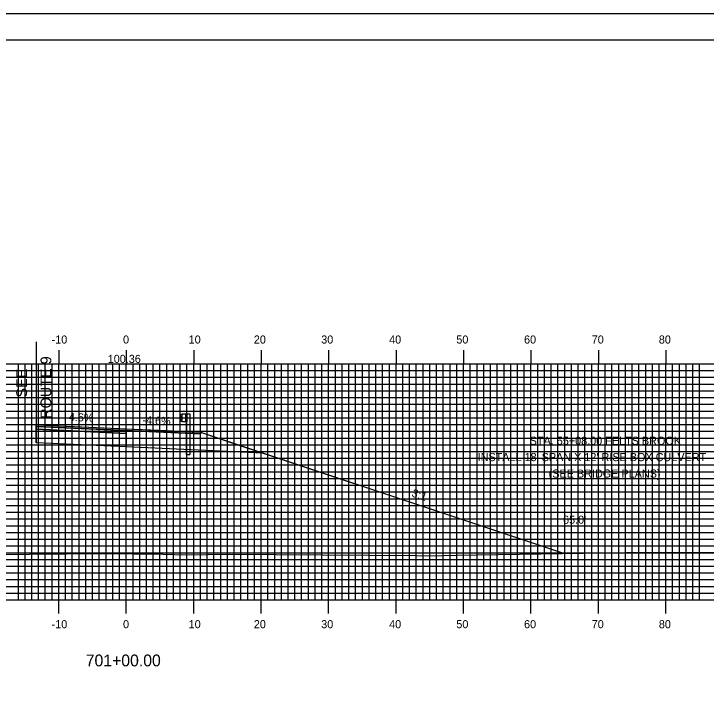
# Model space of a CAD drawing. Extents: x 852542 to 852886, y 364366 to 364586.
# Drawn here: x 852691.5 to 852794.1, y 364484.7 to 364585.7 of the extents above; entities that cross this region are included whole.
import ezdxf

# ---------------------------------------------------------------- set-up
doc = ezdxf.new("R2010")
doc.units = 0
for name, color, linetype in [('ANNOTATION', 7, 'Continuous'), ('BORDER', 7, 'Continuous'), ('D_Guardrail_Beam_Rt', 7, 'Continuous'), ('D_Roadway_Centerline', 7, 'Continuous'), ('D_Roadway_Centerline_Text', 7, 'Continuous'), ('D_Roadway_Edge_Shoulder', 7, 'Continuous'), ('D_Roadway_Edge_TW', 7, 'Continuous'), ('D_Roadway_Pavement', 7, 'Continuous'), ('D_Roadway_SlopeLines', 7, 'Continuous'), ('D_Roadway_SubGrade', 7, 'Continuous'), ('D_Text_Standard', 7, 'Continuous'), ('H_V ANNOTATION', 7, 'Continuous'), ('MAJOR', 7, 'Continuous'), ('MINOR', 7, 'Continuous'), ('PLOT BOUNDARY', 7, 'Continuous'), ('S_Roadway_Centerline', 7, 'Continuous')]:
    doc.layers.add(name, color=color, linetype=linetype)

msp = doc.modelspace()

# ---------------------------------------------------------------- linework, layer by layer
at = {"layer": 'BORDER'}
msp.add_lwpolyline([(852558.58, 364371.79), (852878.58, 364371.79), (852878.58, 364581.79), (852558.58, 364581.79)], close=True, dxfattribs=at)
at = {"layer": 'D_Guardrail_Beam_Rt'}
for p, q in [((852716.36, 364526.26), (852716.22, 364526.16)), ((852716.22, 364526.02), (852716.41, 364525.88)), ((852716.45, 364526.28), (852716.38, 364526.26)), ((852716.45, 364526.36), (852717.14, 364526.36)), ((852716.45, 364525.2), (852716.45, 364526.36)), ((852716.97, 364526.36), (852716.97, 364525.2)), ((852717.07, 364526.36), (852717.07, 364525.2)), ((852717.14, 364526.36), (852717.61, 364526.36)), ((852717.14, 364526.36), (852717.14, 364525.2)), ((852717.61, 364526.36), (852717.61, 364520.36)), ((852716.41, 364525.68), (852716.22, 364525.54)), ((852716.22, 364525.4), (852716.36, 364525.3)), ((852716.38, 364525.29), (852716.45, 364525.28)), ((852716.44, 364525.81), (852716.44, 364525.74)), ((852717.14, 364525.2), (852716.45, 364525.2)), ((852717.12, 364520.36), (852717.12, 364525.2)), ((852717.12, 364520.36), (852717.61, 364520.36))]:
    msp.add_line(p, q, dxfattribs=at)
for centre, major_axis, start_param, end_param in [((852716.27, 364526.09), (-0.0877, 0), 5.323254, 7.243116), ((852716.38, 364526.22), (-0.0417, 0), 4.907132, 5.323254), ((852716.27, 364525.47), (-0.0877, 0), 5.323254, 7.243116), ((852716.38, 364525.33), (-0.0417, 0), 0.959931, 1.376053), ((852716.37, 364525.81), (0.0789, 0), 0, 0.959931), ((852716.37, 364525.74), (0.0789, 0), 5.323254, 6.283185)]:
    msp.add_ellipse(centre, major_axis=major_axis, ratio=0.995501, start_param=start_param, end_param=end_param, dxfattribs=at)
at = {"layer": 'D_Roadway_Centerline'}
msp.add_lwpolyline([(852694.81, 364524.76), (852698.22, 364524.6), (852708.18, 364524.15), (852712.95, 364523.93), (852716.18, 364523.78), (852717.96, 364523.7), (852719.18, 364523.64), (852724.71, 364521.8), (852728.46, 364520.55), (852755.36, 364511.58), (852773.13, 364505.66)], dxfattribs=at)
at = {"layer": 'D_Roadway_Edge_Shoulder'}
for points in [[(852708.18, 364524.15), (852719.18, 364523.64), (852719.18, 364523.39), (852708.18, 364523.9)], [(852708.18, 364524.15), (852716.18, 364523.78), (852716.18, 364523.78), (852719.18, 364523.64), (852719.18, 364523.39), (852708.18, 364523.9)], [(852708.18, 364524.15), (852716.18, 364523.78), (852716.18, 364523.78), (852719.18, 364523.64), (852719.18, 364523.39), (852708.18, 364523.9)], [(852708.18, 364524.15), (852719.18, 364523.64), (852719.18, 364523.39), (852708.18, 364523.9)], [(852708.18, 364524.15), (852719.18, 364523.64), (852719.18, 364523.39), (852708.18, 364523.9)]]:
    msp.add_lwpolyline(points, close=True, dxfattribs=at)
at = {"layer": 'D_Roadway_Edge_TW'}
msp.add_lwpolyline([(852694.81, 364524.76), (852708.18, 364524.15), (852708.18, 364523.9), (852694.81, 364524.51)], close=True, dxfattribs=at)
msp.add_lwpolyline([(852694.81, 364524.76), (852708.18, 364524.15), (852708.18, 364523.9), (852694.81, 364524.51)], close=True, dxfattribs=at)
msp.add_lwpolyline([(852694.81, 364524.76), (852708.18, 364524.15), (852708.18, 364523.9), (852694.81, 364524.51)], close=True, dxfattribs=at)
msp.add_lwpolyline([(852694.81, 364524.76), (852708.18, 364524.15), (852708.18, 364523.9), (852694.81, 364524.51)], dxfattribs=at)
at = {"layer": 'D_Roadway_Pavement'}
msp.add_lwpolyline([(852694.81, 364524.51), (852708.18, 364523.9), (852708.18, 364523.48), (852694.81, 364524.09)], close=True, dxfattribs=at)
msp.add_lwpolyline([(852694.81, 364524.51), (852708.18, 364523.9), (852708.18, 364523.48), (852694.81, 364524.09)], close=True, dxfattribs=at)
msp.add_lwpolyline([(852694.81, 364524.51), (852708.18, 364523.9), (852708.18, 364523.48), (852694.81, 364524.09)], close=True, dxfattribs=at)
msp.add_lwpolyline([(852694.81, 364524.51), (852708.18, 364523.9), (852708.18, 364523.48), (852694.81, 364524.09)], close=True, dxfattribs=at)
msp.add_lwpolyline([(852708.18, 364523.9), (852708.18, 364523.48)], dxfattribs=at)
msp.add_lwpolyline([(852708.18, 364523.9), (852708.18, 364523.48)], dxfattribs=at)
msp.add_lwpolyline([(852708.18, 364523.9), (852708.18, 364523.48)], dxfattribs=at)
msp.add_lwpolyline([(852708.18, 364523.9), (852708.18, 364523.48)], dxfattribs=at)
msp.add_lwpolyline([(852708.18, 364523.9), (852708.18, 364523.48)], dxfattribs=at)
msp.add_lwpolyline([(852708.18, 364523.9), (852708.18, 364523.48)], dxfattribs=at)
msp.add_lwpolyline([(852708.18, 364523.9), (852708.18, 364523.48)], dxfattribs=at)
msp.add_lwpolyline([(852708.18, 364523.9), (852708.18, 364523.48)], dxfattribs=at)
msp.add_lwpolyline([(852708.18, 364523.9), (852708.18, 364523.48)], dxfattribs=at)
msp.add_lwpolyline([(852708.18, 364523.9), (852708.18, 364523.48)], dxfattribs=at)
msp.add_lwpolyline([(852708.18, 364523.9), (852708.18, 364523.48)], dxfattribs=at)
msp.add_lwpolyline([(852708.18, 364523.9), (852708.18, 364523.48)], dxfattribs=at)
msp.add_lwpolyline([(852708.18, 364523.9), (852708.18, 364523.48)], dxfattribs=at)
msp.add_lwpolyline([(852708.18, 364523.9), (852708.18, 364523.48)], dxfattribs=at)
at = {"layer": 'D_Roadway_SlopeLines'}
msp.add_lwpolyline([(852719.18, 364523.64), (852773.13, 364505.66)], dxfattribs=at)
msp.add_lwpolyline([(852719.18, 364523.64), (852773.13, 364505.66)], dxfattribs=at)
msp.add_lwpolyline([(852719.18, 364523.64), (852773.13, 364505.66)], dxfattribs=at)
msp.add_lwpolyline([(852719.18, 364523.64), (852773.13, 364505.66)], dxfattribs=at)
at = {"layer": 'D_Roadway_SubGrade'}
msp.add_line((852694.81, 364537.05), (852694.81, 364522.09), dxfattribs=at)
for points in [[(852694.81, 364524.09), (852708.18, 364523.48), (852708.18, 364521.48), (852694.81, 364522.09)], [(852694.81, 364524.09), (852708.18, 364523.48), (852708.18, 364521.48), (852694.81, 364522.09)], [(852694.81, 364524.09), (852708.18, 364523.48), (852708.18, 364521.48), (852694.81, 364522.09)], [(852694.81, 364524.09), (852708.18, 364523.48), (852708.18, 364521.48), (852694.81, 364522.09)], [(852708.18, 364523.48), (852708.18, 364523.9), (852719.18, 364523.39), (852719.18, 364523.64), (852728.46, 364520.55), (852708.18, 364521.48)], [(852708.18, 364523.48), (852708.18, 364523.9), (852719.18, 364523.39), (852719.18, 364523.64), (852728.46, 364520.55), (852708.18, 364521.48)], [(852708.18, 364523.48), (852708.18, 364523.9), (852719.18, 364523.39), (852719.18, 364523.64), (852728.46, 364520.55), (852708.18, 364521.48)], [(852708.18, 364523.48), (852708.18, 364523.9), (852719.18, 364523.39), (852719.18, 364523.64), (852728.46, 364520.55), (852708.18, 364521.48)]]:
    msp.add_lwpolyline(points, close=True, dxfattribs=at)
at = {"layer": 'MAJOR'}
for p, q in [((852698.18, 364535.79), (852698.18, 364533.79)), ((852708.18, 364535.79), (852708.18, 364533.79)), ((852718.18, 364535.79), (852718.18, 364533.79)), ((852728.18, 364535.79), (852728.18, 364533.79)), ((852738.18, 364535.79), (852738.18, 364533.79)), ((852748.18, 364535.79), (852748.18, 364533.79)), ((852758.18, 364535.79), (852758.18, 364533.79)), ((852768.18, 364535.79), (852768.18, 364533.79)), ((852778.18, 364535.79), (852778.18, 364533.79)), ((852788.18, 364535.79), (852788.18, 364533.79)), ((852568.18, 364533.79), (852848.18, 364533.79)), ((852568.18, 364533.79), (852848.18, 364533.79)), ((852698.18, 364498.79), (852698.18, 364533.79)), ((852708.18, 364498.79), (852708.18, 364533.79)), ((852718.18, 364498.79), (852718.18, 364533.79)), ((852728.18, 364498.79), (852728.18, 364533.79)), ((852738.18, 364498.79), (852738.18, 364533.79)), ((852748.18, 364498.79), (852748.18, 364533.79)), ((852758.18, 364498.79), (852758.18, 364533.79)), ((852768.18, 364498.79), (852768.18, 364533.79)), ((852778.18, 364498.79), (852778.18, 364533.79)), ((852788.18, 364498.79), (852788.18, 364533.79)), ((852568.18, 364528.79), (852848.18, 364528.79)), ((852568.18, 364523.79), (852848.18, 364523.79)), ((852568.18, 364518.79), (852848.18, 364518.79)), ((852568.18, 364513.79), (852848.18, 364513.79)), ((852568.18, 364508.79), (852848.18, 364508.79)), ((852568.18, 364503.79), (852848.18, 364503.79)), ((852568.18, 364498.79), (852848.18, 364498.79)), ((852568.18, 364498.79), (852848.18, 364498.79)), ((852698.18, 364496.78), (852698.18, 364498.79)), ((852708.18, 364496.78), (852708.18, 364498.79)), ((852718.18, 364496.78), (852718.18, 364498.79)), ((852728.18, 364496.78), (852728.18, 364498.79)), ((852738.18, 364496.78), (852738.18, 364498.79)), ((852748.18, 364496.78), (852748.18, 364498.79)), ((852758.18, 364496.78), (852758.18, 364498.79)), ((852768.18, 364496.78), (852768.18, 364498.79)), ((852778.18, 364496.78), (852778.18, 364498.79)), ((852788.18, 364496.78), (852788.18, 364498.79))]:
    msp.add_line(p, q, dxfattribs=at)
at = {"layer": 'MINOR'}
for p, q in [((852692.18, 364498.79), (852692.18, 364533.79)), ((852693.18, 364498.79), (852693.18, 364533.79)), ((852694.18, 364498.79), (852694.18, 364533.79)), ((852695.18, 364498.79), (852695.18, 364533.79)), ((852696.18, 364498.79), (852696.18, 364533.79)), ((852697.18, 364498.79), (852697.18, 364533.79)), ((852699.18, 364498.79), (852699.18, 364533.79)), ((852700.18, 364498.79), (852700.18, 364533.79)), ((852701.18, 364498.79), (852701.18, 364533.79)), ((852702.18, 364498.79), (852702.18, 364533.79)), ((852703.18, 364498.79), (852703.18, 364533.79)), ((852704.18, 364498.79), (852704.18, 364533.79)), ((852705.18, 364498.79), (852705.18, 364533.79)), ((852706.18, 364498.79), (852706.18, 364533.79)), ((852707.18, 364498.79), (852707.18, 364533.79)), ((852709.18, 364498.79), (852709.18, 364533.79)), ((852710.18, 364498.79), (852710.18, 364533.79)), ((852711.18, 364498.79), (852711.18, 364533.79)), ((852712.18, 364498.79), (852712.18, 364533.79)), ((852713.18, 364498.79), (852713.18, 364533.79)), ((852714.18, 364498.79), (852714.18, 364533.79)), ((852715.18, 364498.79), (852715.18, 364533.79)), ((852716.18, 364498.79), (852716.18, 364533.79)), ((852717.18, 364498.79), (852717.18, 364533.79)), ((852719.18, 364498.79), (852719.18, 364533.79)), ((852720.18, 364498.79), (852720.18, 364533.79)), ((852721.18, 364498.79), (852721.18, 364533.79)), ((852722.18, 364498.79), (852722.18, 364533.79)), ((852723.18, 364498.79), (852723.18, 364533.79)), ((852724.18, 364498.79), (852724.18, 364533.79)), ((852725.18, 364498.79), (852725.18, 364533.79)), ((852726.18, 364498.79), (852726.18, 364533.79)), ((852727.18, 364498.79), (852727.18, 364533.79)), ((852729.18, 364498.79), (852729.18, 364533.79)), ((852730.18, 364498.79), (852730.18, 364533.79)), ((852731.18, 364498.79), (852731.18, 364533.79)), ((852732.18, 364498.79), (852732.18, 364533.79)), ((852733.18, 364498.79), (852733.18, 364533.79)), ((852734.18, 364498.79), (852734.18, 364533.79)), ((852735.18, 364498.79), (852735.18, 364533.79)), ((852736.18, 364498.79), (852736.18, 364533.79)), ((852737.18, 364498.79), (852737.18, 364533.79)), ((852739.18, 364498.79), (852739.18, 364533.79)), ((852740.18, 364498.79), (852740.18, 364533.79)), ((852741.18, 364498.79), (852741.18, 364533.79)), ((852742.18, 364498.79), (852742.18, 364533.79)), ((852743.18, 364498.79), (852743.18, 364533.79)), ((852744.18, 364498.79), (852744.18, 364533.79)), ((852745.18, 364498.79), (852745.18, 364533.79)), ((852746.18, 364498.79), (852746.18, 364533.79)), ((852747.18, 364498.79), (852747.18, 364533.79)), ((852749.18, 364498.79), (852749.18, 364533.79)), ((852750.18, 364498.79), (852750.18, 364533.79)), ((852751.18, 364498.79), (852751.18, 364533.79)), ((852752.18, 364498.79), (852752.18, 364533.79)), ((852753.18, 364498.79), (852753.18, 364533.79)), ((852754.18, 364498.79), (852754.18, 364533.79)), ((852755.18, 364498.79), (852755.18, 364533.79)), ((852756.18, 364498.79), (852756.18, 364533.79)), ((852757.18, 364498.79), (852757.18, 364533.79)), ((852759.18, 364498.79), (852759.18, 364533.79)), ((852760.18, 364498.79), (852760.18, 364533.79)), ((852761.18, 364498.79), (852761.18, 364533.79)), ((852762.18, 364498.79), (852762.18, 364533.79)), ((852763.18, 364498.79), (852763.18, 364533.79)), ((852764.18, 364498.79), (852764.18, 364533.79)), ((852765.18, 364498.79), (852765.18, 364533.79)), ((852766.18, 364498.79), (852766.18, 364533.79)), ((852767.18, 364498.79), (852767.18, 364533.79)), ((852769.18, 364498.79), (852769.18, 364533.79)), ((852770.18, 364498.79), (852770.18, 364533.79)), ((852771.18, 364498.79), (852771.18, 364533.79)), ((852772.18, 364498.79), (852772.18, 364533.79)), ((852773.18, 364498.79), (852773.18, 364533.79)), ((852774.18, 364498.79), (852774.18, 364533.79)), ((852775.18, 364498.79), (852775.18, 364533.79)), ((852776.18, 364498.79), (852776.18, 364533.79)), ((852777.18, 364498.79), (852777.18, 364533.79)), ((852779.18, 364498.79), (852779.18, 364533.79)), ((852780.18, 364498.79), (852780.18, 364533.79)), ((852781.18, 364498.79), (852781.18, 364533.79)), ((852782.18, 364498.79), (852782.18, 364533.79)), ((852783.18, 364498.79), (852783.18, 364533.79)), ((852784.18, 364498.79), (852784.18, 364533.79)), ((852785.18, 364498.79), (852785.18, 364533.79)), ((852786.18, 364498.79), (852786.18, 364533.79)), ((852787.18, 364498.79), (852787.18, 364533.79)), ((852789.18, 364498.79), (852789.18, 364533.79)), ((852790.18, 364498.79), (852790.18, 364533.79)), ((852791.18, 364498.79), (852791.18, 364533.79)), ((852792.18, 364498.79), (852792.18, 364533.79)), ((852793.18, 364498.79), (852793.18, 364533.79)), ((852568.18, 364532.79), (852848.18, 364532.79)), ((852568.18, 364531.79), (852848.18, 364531.79)), ((852568.18, 364530.79), (852848.18, 364530.79)), ((852568.18, 364529.79), (852848.18, 364529.79)), ((852568.18, 364527.79), (852848.18, 364527.79)), ((852568.18, 364526.79), (852848.18, 364526.79)), ((852568.18, 364525.79), (852848.18, 364525.79)), ((852568.18, 364524.79), (852848.18, 364524.79)), ((852568.18, 364522.79), (852848.18, 364522.79)), ((852568.18, 364521.79), (852848.18, 364521.79)), ((852568.18, 364520.79), (852848.18, 364520.79)), ((852568.18, 364519.79), (852848.18, 364519.79)), ((852568.18, 364517.79), (852848.18, 364517.79)), ((852568.18, 364516.79), (852848.18, 364516.79)), ((852568.18, 364515.79), (852848.18, 364515.79)), ((852568.18, 364514.79), (852848.18, 364514.79)), ((852568.18, 364512.79), (852848.18, 364512.79)), ((852568.18, 364511.79), (852848.18, 364511.79)), ((852568.18, 364510.79), (852848.18, 364510.79)), ((852568.18, 364509.79), (852848.18, 364509.79)), ((852568.18, 364507.79), (852848.18, 364507.79)), ((852568.18, 364506.79), (852848.18, 364506.79)), ((852568.18, 364505.79), (852848.18, 364505.79)), ((852568.18, 364504.79), (852848.18, 364504.79)), ((852568.18, 364502.79), (852848.18, 364502.79)), ((852568.18, 364501.79), (852848.18, 364501.79)), ((852568.18, 364500.79), (852848.18, 364500.79)), ((852568.18, 364499.79), (852848.18, 364499.79))]:
    msp.add_line(p, q, dxfattribs=at)
at = {"layer": 'PLOT BOUNDARY'}
msp.add_lwpolyline([(852542.39, 364365.67), (852882.39, 364365.67), (852882.39, 364585.67), (852542.39, 364585.67)], close=True, dxfattribs=at)
at = {"layer": 'S_Roadway_Centerline'}
msp.add_lwpolyline([(852688.24, 364505.51), (852704.86, 364505.68), (852713.61, 364505.59), (852717.09, 364505.47), (852723.54, 364505.56), (852751.09, 364505.36), (852753.15, 364505.3), (852757.09, 364505.41), (852769.63, 364505.6), (852782.33, 364505.81), (852787.57, 364505.85), (852792.86, 364505.83), (852801.61, 364505.86), (852805.73, 364505.68), (852820.64, 364505.29), (852825.12, 364505.22), (852826.46, 364505.21), (852827.26, 364505.17), (852848.18, 364504.66)], dxfattribs=at)

# ---------------------------------------------------------------- texts
at = {"layer": 'ANNOTATION'}
for s, height, rotation, p in [('ROUTE 9', 1.6, 90, (852697.07, 364525.63)), ('SEE', 1.6, 90, (852693.47, 364528.78)), ('4.6%', 1.2, 357.3935, (852699.64, 364525.34)), ('-4.6%', 1.2, 357.3663, (852710.55, 364524.87)), ('3:1', 1.2, 341.5651, (852750.4, 364514.14))]:
    msp.add_text(s, height=height, rotation=rotation, dxfattribs=at).set_placement(p)
for s, p in [('STA. 55+08.00 FELTS BROOK', (852767.99, 364521.79)), ("INSTALL 18' SPAN X 12' RISE BOX CULVERT", (852760.27, 364519.36)), ('(SEE BRIDGE PLANS)', (852770.8, 364516.92))]:
    msp.add_text(s, height=1.2, dxfattribs=at).set_placement(p)
at = {"layer": 'D_Roadway_Centerline_Text'}
msp.add_text('100.36', height=1.2, dxfattribs=at).set_placement((852705.43, 364533.92))
at = {"layer": 'D_Text_Standard'}
msp.add_text("65.0'", height=1.2, dxfattribs=at).set_placement((852772.93, 364510.08))
at = {"layer": 'H_V ANNOTATION'}
for s, height, p in [('-10', 1.2, (852697.11, 364536.79)), ('0', 1.2, (852707.7, 364536.79)), ('10', 1.2, (852717.43, 364536.79)), ('20', 1.2, (852727.09, 364536.79)), ('30', 1.2, (852737.08, 364536.79)), ('40', 1.2, (852747.15, 364536.79)), ('50', 1.2, (852757.11, 364536.79)), ('60', 1.2, (852767.15, 364536.79)), ('70', 1.2, (852777.18, 364536.79)), ('80', 1.2, (852787.13, 364536.79)), ('-10', 1.2, (852697.11, 364494.59)), ('0', 1.2, (852707.7, 364494.59)), ('10', 1.2, (852717.43, 364494.59)), ('20', 1.2, (852727.09, 364494.59)), ('30', 1.2, (852737.08, 364494.59)), ('40', 1.2, (852747.15, 364494.59)), ('50', 1.2, (852757.11, 364494.59)), ('60', 1.2, (852767.15, 364494.59)), ('70', 1.2, (852777.18, 364494.59)), ('80', 1.2, (852787.13, 364494.59)), ('701+00.00', 1.75, (852702.17, 364488.94))]:
    msp.add_text(s, height=height, dxfattribs=at).set_placement(p)

doc.saveas('drawing.dxf')
